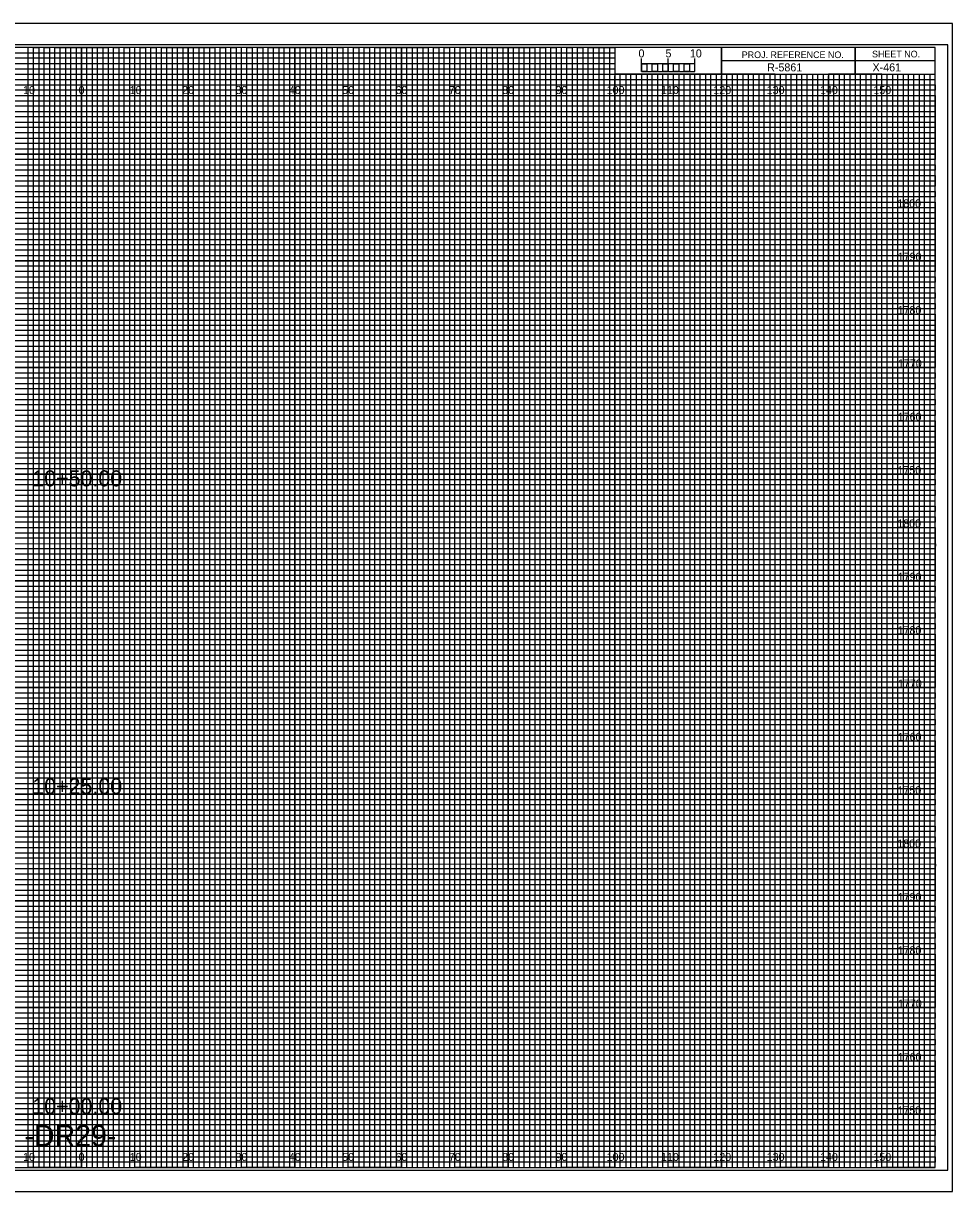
# Model space of a CAD drawing. Extents: x -13 to 323, y -5 to 874.
# Drawn here: x 149.1 to 323.3, y -4.5 to 214.5 of the extents above; entities that cross this region are included whole.
import ezdxf

# ---------------------------------------------------------------- set-up
doc = ezdxf.new("R2010")
doc.units = 0
for name, color, linetype in [('Prop Horizontal Alignment', 7, 'Continuous'), ('Prop XS Alignment Label', 7, 'Continuous'), ('Prop XS Bar Scale Labels', 7, 'Continuous'), ('Prop XS DDE', 7, 'Continuous'), ('Prop XS DDE Elevations', 7, 'Continuous'), ('Prop XS DDE Slope Text', 7, 'Continuous'), ('Prop XS Gore Control Minimum', 7, 'Continuous'), ('Prop XS Project Number', 7, 'Continuous'), ('Prop XS Sheet Number', 7, 'Continuous'), ('Prop XS Shoulder Borrow Shape', 7, 'Continuous'), ('Raster_Level_0', 7, 'Continuous'), ('Scratch_Level_3', 7, 'Continuous'), ('Sheet Cross Section Scale CELL', 7, 'Continuous'), ('Sheet Cutting Line CELL', 7, 'Continuous'), ('Sheet DOT Grid CELL', 7, 'Continuous'), ('Sheet Plot Border Inside CELL', 7, 'Continuous'), ('Sheet Plot Border Outside CELL', 7, 'Continuous')]:
    doc.layers.add(name, color=color, linetype=linetype)

msp = doc.modelspace()

# ---------------------------------------------------------------- linework, layer by layer
at = {"layer": 'Prop XS DDE'}
for p, q in [((0, 209), (260, 209)), ((260, 209), (260, 207.98)), ((260, 207.98), (0, 207.98)), ((0, 207), (260, 207)), ((260, 205.89), (0, 205.89)), ((260, 207), (260, 205.89)), ((0, 204), (320, 204))]:
    msp.add_line(p, q, dxfattribs=at)
for points in [[(0, 203), (270, 203), (320, 203), (320, 202), (0, 202)], [(0, 201), (320, 201), (320, 199), (0, 199)], [(0, 198), (320, 198), (320, 197), (0, 196.98)], [(0, 196), (320, 196), (320, 194), (0, 194)], [(0, 193), (320, 193), (320, 192), (0, 192)], [(0, 191), (320, 191), (320, 189), (0, 189)], [(0, 188), (320, 188), (320, 187), (0, 187)], [(0, 186), (320, 186), (320, 184), (0, 184)], [(0, 183), (320, 183), (320, 182), (0, 182)], [(0, 181), (320, 181), (320, 179), (0, 179)], [(0, 178), (320, 178), (320, 177), (0, 177)], [(0, 176), (320, 176), (320, 173.95), (320, 173), (320, 172), (0, 172)], [(0, 174), (320, 174), (320, 173), (0, 173)], [(0, 171), (320, 171), (320, 169), (0, 169.03)], [(0, 169.03), (320, 169), (320, 168), (0, 168)], [(0, 167), (320, 167), (320, 166), (0, 166)], [(0, 164), (320, 164), (320, 163), (0, 163)], [(0, 162), (320, 162), (320, 161), (0, 161)], [(-0.07, 158.89), (320, 158.89), (320, 157.88), (-0.07, 157.88)], [(0, 157), (320, 157), (320, 156), (0, 156)], [(0, 154), (320, 154), (320, 153), (0, 153)], [(0, 152), (320, 152), (320, 151), (0, 151)], [(0, 149), (320, 149), (320, 148), (0, 148)], [(0, 147), (320, 147), (320, 146), (0, 146)], [(0, 144), (320, 144), (320, 143), (0, 143)], [(0, 142), (320, 142), (320, 141), (0, 141)], [(0, 139), (320, 139), (319.99, 137.98), (0, 138)], [(0, 137), (320, 137), (320, 136), (0, 136)], [(0, 134), (320, 134), (320, 133), (0, 133)], [(0, 132), (320, 132), (320, 131), (0, 131)], [(0, 129), (320, 129), (320, 128), (0, 128)], [(0, 127), (320, 127), (320, 126), (0, 126)], [(0, 124), (320, 124), (320, 123), (0, 123)], [(0, 122), (320, 122), (320, 121), (0, 121)], [(0, 119), (320, 119), (320, 118), (0, 118)], [(0, 116.99), (320.07, 116.91), (320, 116), (0, 116)], [(0, 114), (320, 114), (320, 113), (0, 113)], [(0, 112), (320, 112), (320, 111), (0, 111)], [(0, 109), (320, 109), (320, 108), (0, 108)], [(0, 107), (320, 107), (320, 106), (0, 106)], [(0, 104), (320, 104), (320, 103), (0, 103)], [(0, 102), (320, 102), (320, 101), (0, 101)], [(0, 99), (320, 99), (320, 98), (0, 98)], [(0, 97), (320, 97), (320, 96), (0, 96)], [(0, 94), (320, 94), (320, 93), (0, 93)], [(0, 92), (320, 92), (320, 91), (0, 91)], [(0, 89), (320, 89), (320, 88), (0, 88)], [(0, 87), (320, 87), (320, 86), (0, 86)], [(0, 84), (320, 84), (320, 83), (0, 83)], [(0, 82), (320, 82), (320, 81), (0, 81)], [(0, 79), (320, 79), (319.99, 77.98), (0, 78)], [(0, 77), (320, 77), (320, 76), (0, 76)], [(0, 74), (320, 74), (320, 73), (0, 73)], [(0, 72), (320, 72), (320, 71), (0, 71)], [(0, 69), (320, 69), (320, 68), (0, 68)], [(0, 67), (320, 67), (320, 66), (0, 66)], [(0, 64), (320, 64), (320, 63), (0, 63)], [(0, 62), (320, 62), (320, 61), (0, 61)], [(0, 59), (320, 59), (320, 58), (0, 58)], [(0, 56.99), (320.07, 56.91), (320, 56), (0, 56)], [(0, 54), (320, 54), (320, 53), (0, 53)], [(0, 52), (320, 52), (320, 51), (0, 51)], [(0, 49), (320, 49), (320, 48), (0, 48)], [(0, 47), (320, 47), (320, 46), (0, 46)], [(0, 44), (320, 44), (320, 43), (0, 43)], [(0, 42), (320, 42), (320, 41), (0, 41)], [(0, 39), (320, 39), (320, 38), (0, 38)], [(0, 37), (320, 37), (320, 36), (0, 36)], [(0, 34), (320, 34), (320, 33), (0, 33)], [(0, 32), (320, 32), (320, 31), (0, 31)], [(0, 29), (320, 29), (320, 28), (0, 28)], [(0, 27), (320, 27), (320, 26), (0, 26)], [(0, 24), (320, 24), (320, 23), (0, 23)], [(0, 22), (320, 22), (320, 21), (0, 21)], [(0, 19), (320, 19), (320, 18), (0, 18)], [(0, 17), (320, 17), (320, 16), (0, 16)], [(0, 14), (320, 14), (320, 13), (0, 13)], [(0, 12), (320, 12), (320, 11), (0, 11)], [(0, 9), (320, 9), (320, 8), (0, 8)], [(0, 7), (320, 7), (320, 6), (0, 6)], [(0, 4), (320, 4), (320, 3), (0, 3)], [(0, 2), (320, 2), (320, 1), (0, 1)]]:
    msp.add_lwpolyline(points, dxfattribs=at)
at = {"layer": 'Prop XS DDE Elevations'}
for p, q in [((267, 205), (266.01, 205)), ((266.01, 205), (266.01, 0)), ((267, 0), (267, 205)), ((269, 205), (268, 205)), ((268, 205), (268, 0)), ((269, 0), (269, 205)), ((266.01, 0), (265, 0)), ((268, 0), (267, 0))]:
    msp.add_line(p, q, dxfattribs=at)
for points in [[(150, 0), (151, 0), (151, 210), (152, 210), (152, 0)], [(152, 0), (153, 0), (153, 210), (154, 210), (154, 0)], [(155, 0), (156, 0), (156, 210), (157, 210), (157, 0)], [(157, 0), (158, 0), (158, 210), (159, 210), (159, 0)], [(160, 0), (161, 0), (161, 210), (162, 210), (162, 0)], [(162, 0), (163, 0), (163, 210), (164, 210), (164, 0)], [(165, 0), (166, 0), (166, 210), (167, 210), (167, 0)], [(167, 0), (168, 0), (168, 210), (169, 210), (169, 0)], [(170, 0), (171, 0), (171, 210), (172, 210), (172, 0)], [(172, 0), (173, 0), (173, 210), (174, 210), (174, 0)], [(175, 0), (176, 0), (176, 210), (177, 210), (177, 0)], [(177, 0), (178, 0), (178, 210), (179, 210), (179, 0)], [(180, 0), (181, 0), (181, 210), (182, 210), (182, 0)], [(182, 0), (183, 0), (183, 210), (184, 210), (184, 0)], [(185, 0), (186, 0), (186, 210), (187, 210), (187, 0)], [(187, 0), (188, 0), (188, 210), (189, 210), (189, 0)], [(190, 0), (191, 0), (191, 210), (192, 210), (192, 0)], [(192, 0), (193, 0), (193, 210), (194, 210), (194, 0)], [(195, 0), (196, 0), (196, 210), (197, 210), (197, 0)], [(197, 0), (198, 0), (198, 210), (199, 210), (199, 0)], [(200, 0), (201, 0), (201, 210), (202, 210), (202, 0)], [(202, 0), (203, 0), (203, 210), (204, 210), (204, 0)], [(205, 0), (206, 0), (206, 210), (207, 210), (207, 0)], [(207, 0), (208, 0), (208, 210), (209, 210), (209, 0)], [(210, 0), (211, 0), (211, 210), (212, 210), (212, 0)], [(212, 0), (213, 0), (213, 210), (214, 210), (214, 0)], [(215, 0), (216, 0), (216, 210), (217, 210), (217, 0)], [(217, 0), (218, 0), (218, 210), (219, 210), (219, 0)], [(220, 0), (221, 0), (221, 210), (222, 210), (222, 0)], [(222, 0), (223, 0), (223, 210), (224, 210), (224, 0)], [(225, 0), (226, 0), (226, 210), (227, 210), (227, 0)], [(227, 0), (228, 0), (228, 210), (229, 210), (229, 0)], [(230, 0), (231, 0), (231, 210), (232, 210), (232, 0)], [(232, 0), (233, 0), (233, 210), (234, 210), (234, 0)], [(235, 0), (236, 0), (236, 210), (237, 210), (237, 0)], [(237, 0), (238, 0), (238, 210), (239, 210), (239, 0)], [(240, 0), (241, 0), (241, 210), (242, 210), (242, 0)], [(242, 0), (243, 0), (243, 210), (244, 210), (244, 0)], [(245, 0), (246, 0), (246, 210), (247, 210), (247, 0)], [(247, 0), (248, 0), (248, 210), (249, 210), (249, 0)], [(250, 0), (251, 0), (251, 210), (252, 210), (252, 0)], [(252, 0), (253, 0), (253, 210), (254, 210), (254, 0)], [(255, 0), (256, 0), (256, 210), (257, 210), (257, 0)], [(257, 0), (258, 0), (258, 210), (259, 210), (259, 0)], [(260, 0), (261, 0), (261, 205), (262.02, 205), (262.02, 0)], [(262, 0), (263, 0), (263, 205), (263.99, 205), (263.99, 0)], [(270, 0), (270.98, 0), (270.98, 205), (272, 205), (272, 0)], [(272, 0), (273, 0), (273, 205), (274.05, 205), (274.05, 0)], [(275, 0), (276, 0), (276, 205), (277, 205), (277, 0)], [(277, 0), (278, 0), (278, 205), (279, 205), (279, 0)], [(280, 0), (281, 0), (281, 205), (282, 205), (282, 0)], [(282, 0), (283, 0), (283, 205), (284, 205), (284, 0)], [(285, 0), (286, 0), (286, 205), (287, 205), (287, 0)], [(287, 0), (288, 0), (288, 205), (289, 205), (289, 0)], [(290, 0), (291, 0), (291, 205), (292, 205), (292, 0)], [(292, 0), (293, 0), (293, 205), (294, 205), (294, 0)], [(295, 0), (296, 0), (296, 205), (297, 205), (297, 0)], [(297, 0), (298, 0), (298, 205), (299, 205), (299, 0)], [(300, 0), (301, 0), (301, 205), (302, 205), (302, 0)], [(302, 0), (303, 0), (303, 205), (304, 205), (304, 0)], [(305, 0), (306, 0), (306, 205), (307, 205), (307, 0)], [(307, 0), (308, 0), (308, 205), (309, 205), (309, 0)], [(310, 0), (311, 0), (311, 205), (312, 205), (312, 0)], [(312, 0), (313, 0), (313, 205), (314, 205), (314, 0)], [(315, 0), (316, 0), (316, 205), (317, 205), (317, 0)], [(317, 0), (318, 0), (318, 205), (319, 205), (319, 0)]]:
    msp.add_lwpolyline(points, dxfattribs=at)
at = {"layer": 'Prop XS DDE Slope Text'}
for p, q in [((305, 210), (305, 205)), ((305, 205), (305, 210)), ((280, 207.5), (280, 205)), ((320, 207.49), (280, 207.49)), ((280, 205), (320, 205))]:
    msp.add_line(p, q, dxfattribs=at)
for points in [[(320, 210), (0, 210), (0, 0), (320, 0)], [(280, 210), (260, 210), (260, 205.03), (280, 205.03)], [(320, 210), (280, 210), (280, 205), (320, 205)]]:
    msp.add_lwpolyline(points, close=True, dxfattribs=at)
at = {"layer": 'Prop XS Gore Control Minimum'}
for p, q in [((150, 210), (140, 210)), ((150, 0), (150, 210)), ((170, 210), (160, 210)), ((160, 210), (160, 0)), ((170, 0), (170, 210)), ((190, 210), (180, 210)), ((180, 210), (180, 0)), ((190, 0), (190, 210)), ((210, 210), (200, 210)), ((200, 210), (200, 0)), ((210, 0), (210, 210)), ((230, 210), (220, 210)), ((220, 210), (220, 0)), ((230, 0), (230, 210)), ((250, 210), (240, 210)), ((240, 210), (240, 0)), ((250, 0), (250, 210)), ((260, 210), (260, 0)), ((270, 0), (270, 205)), ((290, 205), (280, 205)), ((280, 205), (280, 0)), ((290, 0), (290, 205)), ((310, 205), (300, 205)), ((300, 205), (300, 0)), ((310, 0), (310, 205)), ((160, 0), (150, 0)), ((180, 0), (170, 0)), ((200, 0), (190, 0)), ((220, 0), (210, 0)), ((240, 0), (230, 0)), ((260, 0), (250, 0)), ((280, 0), (270, 0)), ((300, 0), (290, 0)), ((320, 0), (310, 0)), ((320, 0), (320, 0))]:
    msp.add_line(p, q, dxfattribs=at)
for points in [[(0, 200), (320, 200), (320, 190), (0, 190)], [(0, 180), (320, 180), (320, 170), (0, 170)], [(0, 160), (320, 160), (320, 150), (0, 150)], [(0, 140), (320, 140), (320, 130), (0, 130)], [(0, 120), (320, 120), (320, 110), (0, 110)], [(0, 100), (320, 100), (320, 90), (0, 90)], [(0, 80), (320, 80), (320, 70), (0, 70)], [(0, 60), (320, 60), (320, 50), (0, 50)], [(0, 40), (320, 40), (320, 30), (0, 30)], [(0, 20), (320, 20), (320, 10), (0, 10)]]:
    msp.add_lwpolyline(points, dxfattribs=at)
at = {"layer": 'Prop XS Shoulder Borrow Shape'}
for points in [[(145, 0), (155, 0), (155, 210), (165, 210), (165, 0), (175, 0), (175, 210), (185, 210), (185, 0), (195, 0), (195, 210), (205, 210), (205, 0), (215, 0), (215, 210), (225, 210), (225, 0), (235, 0), (235, 210), (245, 210), (245, 0), (255, 0), (255, 210), (259.93, 210), (260, 210), (260, 205), (264.99, 205), (264.99, 0), (275, 0), (275, 205), (285, 205), (285, 0), (295, 0), (295, 205), (305, 205), (305, 0), (315, 0), (315, 205)], [(0, 205), (275, 205)], [(0, 185), (320, 185), (320, 195), (0, 195)], [(0, 165), (320, 165), (320, 175), (0, 175)], [(0, 145), (320, 145), (320, 155), (0, 155)], [(0, 125), (320, 125), (320, 135), (0, 135)], [(0, 105), (320, 105), (320, 115), (0, 115)], [(0, 85), (320, 85), (320, 95), (0, 95)], [(0, 65), (320, 65), (320, 75), (0, 75)], [(0, 45), (320, 45), (320, 55), (0, 55)], [(0, 25), (320, 25), (320, 35), (0, 35)], [(0, 5), (320, 5), (320, 15), (0, 15)]]:
    msp.add_lwpolyline(points, dxfattribs=at)
at = {"layer": 'Sheet Cross Section Scale CELL'}
for p, q in [((265, 205.49), (265, 207.9)), ((265, 206.9), (265, 207.9)), ((270, 205.49), (270, 207.9)), ((275, 205.49), (275, 207.9)), ((275, 206.9), (275, 207.9))]:
    msp.add_line(p, q, dxfattribs=at)
for points in [[(275, 206.9), (265, 206.9), (265, 205.49), (275, 205.49)], [(265, 206.9), (266, 206.9), (266, 205.49), (265, 205.49)], [(267, 206.9), (268, 206.9), (268, 205.49), (267, 205.49)], [(269, 206.9), (270, 206.9), (270, 205.49), (269, 205.49)], [(271, 206.9), (272, 206.9), (272, 205.49), (271, 205.49)], [(273, 206.9), (274, 206.9), (274, 205.49), (273, 205.49)]]:
    msp.add_lwpolyline(points, close=True, dxfattribs=at)
at = {"layer": 'Sheet Cutting Line CELL'}
for p, q in [((323.3, 214.5), (-13.4, 214.5)), ((-13.4, -4.5), (323.3, -4.5))]:
    msp.add_line(p, q, dxfattribs=at)
at = {"layer": 'Sheet DOT Grid CELL'}
for p, q in [((150, 0), (150, 210)), ((160, 0), (160, 210)), ((170, 0), (170, 210)), ((180, 0), (180, 210)), ((190, 0), (190, 210)), ((200, 0), (200, 210)), ((210, 0), (210, 210)), ((220, 0), (220, 210)), ((230, 0), (230, 210)), ((240, 0), (240, 210)), ((250, 0), (250, 210)), ((260, 0), (260, 204.69)), ((270, 0), (270, 204.69)), ((280, 0), (280, 204.69)), ((290, 0), (290, 204.69)), ((300, 0), (300, 204.69)), ((310, 0), (310, 204.69)), ((0, 200), (320, 200)), ((0, 190), (320, 190)), ((0, 180), (320, 180)), ((0, 170), (320, 170)), ((0, 160), (320, 160)), ((0, 150), (320, 150)), ((0, 140), (320, 140)), ((0, 130), (320, 130)), ((0, 120), (320, 120)), ((0, 110), (320, 110)), ((0, 100), (320, 100)), ((0, 90), (320, 90)), ((0, 80), (320, 80)), ((0, 70), (320, 70)), ((0, 60), (320, 60)), ((0, 50), (320, 50)), ((0, 40), (320, 40)), ((0, 30), (320, 30)), ((0, 20), (320, 20)), ((0, 10), (320, 10))]:
    msp.add_line(p, q, dxfattribs=at)
at = {"layer": 'Sheet Plot Border Inside CELL'}
msp.add_lwpolyline([(-10.8, -0.5), (322.4, -0.5), (322.4, 210.5), (-10.8, 210.5)], close=True, dxfattribs=at)
at = {"layer": 'Sheet Plot Border Outside CELL'}
msp.add_lwpolyline([(-13.4, -4.5), (323.3, -4.5), (323.3, 214.5), (-13.4, 214.5)], close=True, dxfattribs=at)

# ---------------------------------------------------------------- texts
at = {"layer": 'Prop Horizontal Alignment'}
for s, p in [('10+50.00', (150.77, 127.71)), ('10+25.00', (150.77, 70.01)), ('10+00.00', (150.77, 10.02))]:
    msp.add_text(s, height=3, dxfattribs=at).set_placement(p)
at = {"layer": 'Prop XS Alignment Label'}
msp.add_text('-DR29-', height=4, dxfattribs=at).set_placement((149.3, 4))
at = {"layer": 'Prop XS Bar Scale Labels'}
for s, p in [('5', (269.47, 208.12)), ('10', (274.04, 208.12))]:
    msp.add_text(s, height=1.5, dxfattribs=at).set_placement(p)
at = {"layer": 'Prop XS DDE Slope Text'}
for s, p in [('PROJ. REFERENCE NO.', (283.77, 207.99)), ('SHEET NO.', (308.19, 208.12))]:
    msp.add_text(s, height=1.25, dxfattribs=at).set_placement(p)
at = {"layer": 'Prop XS Project Number'}
msp.add_text('R-5861', height=1.5, dxfattribs=at).set_placement((288.53, 205.5))
at = {"layer": 'Prop XS Sheet Number'}
msp.add_text('X-461', height=1.5, dxfattribs=at).set_placement((308.28, 205.5))
at = {"layer": 'Raster_Level_0'}
for s, p in [('10', (149.04, 201.25)), ('0', (159.45, 201.25)), ('0', (159.45, 201.25)), ('10', (169.04, 201.25)), ('20', (178.86, 201.25)), ('30', (188.86, 201.25)), ('40', (198.86, 201.25)), ('50', (208.86, 201.25)), ('60', (218.86, 201.25)), ('70', (228.86, 201.25)), ('80', (238.86, 201.25)), ('90', (248.86, 201.25)), ('100', (258.44, 201.25)), ('110', (268.62, 201.25)), ('120', (278.44, 201.25)), ('130', (288.44, 201.25)), ('140', (298.44, 201.25)), ('150', (308.44, 201.25)), ('10', (149.04, 1.25)), ('0', (159.45, 1.25)), ('0', (159.45, 1.25)), ('10', (169.04, 1.25)), ('20', (178.86, 1.25)), ('30', (188.86, 1.25)), ('40', (198.86, 1.25)), ('50', (208.86, 1.25)), ('60', (218.86, 1.25)), ('70', (228.86, 1.25)), ('80', (238.86, 1.25)), ('90', (248.86, 1.25)), ('100', (258.44, 1.25)), ('110', (268.62, 1.25)), ('120', (278.44, 1.25)), ('130', (288.44, 1.25)), ('140', (298.44, 1.25)), ('150', (308.44, 1.25))]:
    msp.add_text(s, height=1.5, dxfattribs=at).set_placement(p)
at = {"layer": 'Scratch_Level_3'}
for s, p in [('1800', (312.92, 180)), ('1790', (313, 170)), ('1780', (312.98, 160)), ('1770', (313.04, 150)), ('1760', (313, 140)), ('1750', (312.96, 130)), ('1800', (312.92, 120)), ('1790', (313, 110)), ('1780', (312.98, 100)), ('1770', (313.04, 90)), ('1760', (313, 80)), ('1750', (312.96, 70)), ('1800', (312.92, 60)), ('1790', (313, 50)), ('1780', (312.98, 40)), ('1770', (313.04, 30)), ('1760', (313, 20)), ('1750', (312.96, 10))]:
    msp.add_text(s, height=1.5, dxfattribs=at).set_placement(p)
at = {"layer": 'Sheet Cross Section Scale CELL'}
msp.add_text('0', height=1.5, dxfattribs=at).set_placement((264.41, 208.12))

doc.saveas('drawing.dxf')
